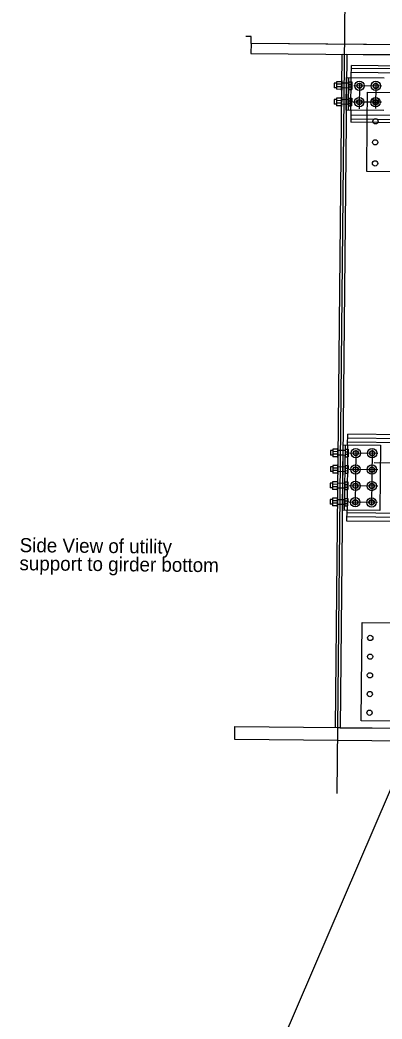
# Model space of a CAD drawing. Extents: x 632312 to 632885, y 378199 to 378534.
# Drawn here: x 632716.99 to 632723.43, y 378443.12 to 378460.93 of the extents above; entities that cross this region are included whole.
import ezdxf

# ---------------------------------------------------------------- set-up
doc = ezdxf.new("R2010")
doc.units = 0
for name, color, linetype in [('B_Boring', 7, 'Continuous'), ('B_Boring Annot', 7, 'Continuous'), ('R_Proposed Const Limits Cut', 7, 'Continuous'), ('R_Shade Removal', 7, 'Continuous'), ('R_Wall', 7, 'Continuous'), ('SHT_Dimensions', 7, 'Continuous'), ('USACE_Easement', 7, 'Continuous')]:
    doc.layers.add(name, color=color, linetype=linetype)

msp = doc.modelspace()

# ---------------------------------------------------------------- linework, layer by layer
at = {"layer": 'B_Boring'}
for p, q in [((632722.888, 378459.902), (632722.89, 378460.114)), ((632733.89, 378460.005), (632722.89, 378460.114)), ((632733.889, 378459.954), (632722.89, 378460.064)), ((632722.585, 378459.8), (632722.584, 378459.717)), ((632722.627, 378459.8), (632722.585, 378459.8)), ((632722.627, 378459.826), (632722.626, 378459.691)), ((632722.71, 378459.825), (632722.627, 378459.826)), ((632722.71, 378459.78), (632722.627, 378459.781)), ((632722.711, 378459.841), (632722.709, 378459.674)), ((632722.721, 378459.841), (632722.711, 378459.841)), ((632722.721, 378459.841), (632722.719, 378459.674)), ((632722.799, 378459.319), (632722.805, 378459.902)), ((632722.805, 378459.902), (632723.472, 378459.896)), ((632722.841, 378459.319), (632722.847, 378459.902)), ((632722.846, 378459.824), (632722.844, 378459.688)), ((632722.845, 378459.779), (632722.897, 378459.778)), ((632722.846, 378459.824), (632722.898, 378459.823)), ((632722.898, 378459.823), (632722.897, 378459.688)), ((632722.626, 378459.717), (632722.584, 378459.717)), ((632722.71, 378459.735), (632722.626, 378459.736)), ((632722.709, 378459.69), (632722.626, 378459.691)), ((632722.719, 378459.674), (632722.709, 378459.674)), ((632722.844, 378459.688), (632722.897, 378459.688)), ((632722.845, 378459.734), (632722.897, 378459.733)), ((632722.582, 378459.509), (632722.581, 378459.425)), ((632722.623, 378459.425), (632722.581, 378459.425)), ((632722.624, 378459.508), (632722.582, 378459.509)), ((632722.624, 378459.534), (632722.623, 378459.399)), ((632722.707, 378459.443), (632722.623, 378459.444)), ((632722.708, 378459.533), (632722.624, 378459.534)), ((632722.707, 378459.488), (632722.624, 378459.489)), ((632722.708, 378459.549), (632722.706, 378459.382)), ((632722.718, 378459.549), (632722.708, 378459.549)), ((632722.718, 378459.549), (632722.716, 378459.382)), ((632722.843, 378459.532), (632722.842, 378459.397)), ((632722.842, 378459.487), (632722.895, 378459.486)), ((632722.842, 378459.442), (632722.894, 378459.441)), ((632722.843, 378459.532), (632722.895, 378459.532)), ((632722.895, 378459.532), (632722.894, 378459.396)), ((632722.706, 378459.398), (632722.623, 378459.399)), ((632722.716, 378459.382), (632722.706, 378459.382)), ((632723.466, 378459.312), (632722.799, 378459.319)), ((632722.842, 378459.397), (632722.894, 378459.396)), ((632722.882, 378459.318), (632722.88, 378459.106)), ((632733.88, 378458.996), (632722.88, 378459.106)), ((632733.88, 378459.047), (632722.881, 378459.156)), ((632723.163, 378458.227), (632723.172, 378459.103)), ((632724.173, 378458.217), (632723.163, 378458.227)), ((632722.823, 378453.354), (632722.825, 378453.546)), ((632733.825, 378453.437), (632722.825, 378453.546)), ((632722.74, 378453.355), (632722.728, 378452.189)), ((632722.74, 378453.355), (632723.406, 378453.349)), ((632722.77, 378452.188), (632722.782, 378453.355)), ((632733.824, 378453.364), (632722.824, 378453.474)), ((632723.406, 378453.349), (632723.395, 378452.182)), ((632722.52, 378453.253), (632722.519, 378453.17)), ((632722.561, 378453.17), (632722.519, 378453.17)), ((632722.562, 378453.253), (632722.52, 378453.253)), ((632722.562, 378453.279), (632722.561, 378453.144)), ((632722.644, 378453.188), (632722.561, 378453.189)), ((632722.645, 378453.278), (632722.562, 378453.279)), ((632722.645, 378453.233), (632722.562, 378453.234)), ((632722.645, 378453.294), (632722.644, 378453.127)), ((632722.656, 378453.294), (632722.645, 378453.294)), ((632722.654, 378453.127), (632722.656, 378453.294)), ((632722.739, 378453.251), (632722.655, 378453.252)), ((632722.78, 378453.232), (632722.832, 378453.231)), ((632722.78, 378453.187), (632722.832, 378453.186)), ((632722.781, 378453.277), (632722.833, 378453.276)), ((632722.833, 378453.276), (632722.831, 378453.141)), ((632722.644, 378453.143), (632722.561, 378453.144)), ((632722.643, 378453.002), (632722.641, 378452.835)), ((632722.653, 378453.002), (632722.643, 378453.002)), ((632722.654, 378453.127), (632722.644, 378453.127)), ((632722.651, 378452.835), (632722.653, 378453.002)), ((632722.738, 378453.168), (632722.655, 378453.169)), ((632722.779, 378453.141), (632722.831, 378453.141)), ((632722.517, 378452.962), (632722.516, 378452.878)), ((632722.558, 378452.878), (632722.516, 378452.878)), ((632722.559, 378452.961), (632722.517, 378452.962)), ((632722.559, 378452.987), (632722.558, 378452.852)), ((632722.642, 378452.896), (632722.558, 378452.897)), ((632722.641, 378452.851), (632722.558, 378452.852)), ((632722.642, 378452.986), (632722.559, 378452.987)), ((632722.642, 378452.941), (632722.559, 378452.942)), ((632722.651, 378452.835), (632722.641, 378452.835)), ((632722.776, 378452.85), (632722.829, 378452.849)), ((632722.777, 378452.94), (632722.829, 378452.939)), ((632722.777, 378452.895), (632722.829, 378452.894)), ((632722.778, 378452.985), (632722.83, 378452.985)), ((632722.83, 378452.985), (632722.829, 378452.849)), ((632722.514, 378452.67), (632722.513, 378452.587)), ((632722.556, 378452.67), (632722.514, 378452.67)), ((632722.556, 378452.696), (632722.555, 378452.56)), ((632722.64, 378452.695), (632722.556, 378452.696)), ((632722.639, 378452.65), (632722.556, 378452.651)), ((632722.64, 378452.71), (632722.638, 378452.544)), ((632722.65, 378452.71), (632722.64, 378452.71)), ((632722.648, 378452.544), (632722.65, 378452.71)), ((632722.774, 378452.648), (632722.827, 378452.648)), ((632722.775, 378452.693), (632722.827, 378452.693)), ((632722.827, 378452.693), (632722.826, 378452.558)), ((632722.555, 378452.586), (632722.513, 378452.587)), ((632722.639, 378452.605), (632722.555, 378452.605)), ((632722.638, 378452.559), (632722.555, 378452.56)), ((632722.648, 378452.544), (632722.638, 378452.544)), ((632722.774, 378452.603), (632722.826, 378452.603)), ((632722.774, 378452.558), (632722.826, 378452.558)), ((632722.511, 378452.378), (632722.511, 378452.295)), ((632722.553, 378452.378), (632722.511, 378452.378)), ((632722.552, 378452.295), (632722.511, 378452.295)), ((632722.553, 378452.404), (632722.552, 378452.269)), ((632722.636, 378452.313), (632722.552, 378452.314)), ((632722.637, 378452.403), (632722.553, 378452.404)), ((632722.636, 378452.358), (632722.553, 378452.359)), ((632722.637, 378452.419), (632722.635, 378452.252)), ((632722.647, 378452.419), (632722.637, 378452.419)), ((632722.646, 378452.252), (632722.647, 378452.419)), ((632722.771, 378452.312), (632722.823, 378452.311)), ((632722.772, 378452.402), (632722.824, 378452.401)), ((632722.772, 378452.357), (632722.824, 378452.356)), ((632722.824, 378452.401), (632722.823, 378452.266)), ((632722.635, 378452.268), (632722.552, 378452.269)), ((632722.646, 378452.252), (632722.635, 378452.252)), ((632723.395, 378452.182), (632722.728, 378452.189)), ((632722.771, 378452.266), (632722.823, 378452.266)), ((632722.81, 378451.996), (632722.812, 378452.188)), ((632733.81, 378451.959), (632722.81, 378452.069)), ((632733.809, 378451.887), (632722.81, 378451.996))]:
    msp.add_line(p, q, dxfattribs=at)
for points in [[(632724.434, 378460.298), (632724.436, 378460.475), (632721.103, 378460.508), (632721.101, 378460.331)], [(632722.69, 378448.314), (632722.606, 378448.315), (632722.726, 378460.315), (632722.809, 378460.314)], [(632724.481, 378448.297), (632724.479, 378448.067), (632720.813, 378448.104), (632720.815, 378448.333)]]:
    msp.add_lwpolyline(points, close=True, dxfattribs=at)
for points in [[(632723.765, 378460.105), (632723.767, 378460.304), (632722.809, 378460.314), (632722.69, 378448.314), (632723.648, 378448.305), (632723.649, 378448.43)], [(632724.455, 378449.825), (632724.441, 378448.422), (632724.441, 378448.422), (632724.441, 378448.422), (632723.066, 378448.436), (632723.083, 378450.186), (632724.098, 378450.175)]]:
    msp.add_lwpolyline(points, dxfattribs=at)
for centre in [(632723.033, 378459.754), (632723.324, 378459.751), (632723.03, 378459.463), (632723.321, 378459.46), (632723.322, 378459.496), (632723.318, 378459.121), (632723.314, 378458.746), (632723.311, 378458.371), (632722.968, 378453.207), (632723.259, 378453.204), (632722.965, 378452.916), (632723.256, 378452.913), (632722.962, 378452.624), (632723.253, 378452.621), (632722.959, 378452.332), (632723.25, 378452.329), (632723.226, 378449.913), (632723.223, 378449.58), (632723.22, 378449.247), (632723.217, 378448.913), (632723.213, 378448.58)]:
    msp.add_circle(centre, 0.0469, dxfattribs=at)
at = {"layer": 'B_Boring Annot'}
for p, q in [((632721.104, 378460.631), (632721.008, 378460.63)), ((632721.103, 378460.508), (632721.104, 378460.631)), ((632724.436, 378460.475), (632721.103, 378460.508))]:
    msp.add_line(p, q, dxfattribs=at)
at = {"layer": 'R_Proposed Const Limits Cut'}
for p, q in [((632733.889, 378459.88), (632722.889, 378459.989)), ((632722.846, 378459.798), (632722.721, 378459.799)), ((632722.882, 378459.318), (632722.888, 378459.902)), ((632722.845, 378459.714), (632722.72, 378459.716)), ((632723.172, 378459.103), (632723.177, 378459.643)), ((632723.177, 378459.643), (632724.552, 378459.63)), ((632722.842, 378459.423), (632722.717, 378459.424)), ((632722.843, 378459.506), (632722.718, 378459.507)), ((632733.881, 378459.121), (632722.882, 378459.231)), ((632722.823, 378453.354), (632722.812, 378452.188)), ((632733.823, 378453.291), (632722.824, 378453.4)), ((632722.78, 378453.251), (632722.739, 378453.251)), ((632722.78, 378453.167), (632722.738, 378453.168)), ((632722.777, 378452.876), (632722.652, 378452.877)), ((632722.778, 378452.959), (632722.653, 378452.96)), ((632722.775, 378452.667), (632722.65, 378452.669)), ((632722.774, 378452.584), (632722.649, 378452.585)), ((632722.771, 378452.292), (632722.646, 378452.294)), ((632722.772, 378452.376), (632722.647, 378452.377)), ((632733.811, 378452.033), (632722.811, 378452.142))]:
    msp.add_line(p, q, dxfattribs=at)
for centre, radius in [((632723.033, 378459.754), 0.0833), ((632723.033, 378459.754), 0.0417), ((632723.324, 378459.751), 0.0833), ((632723.324, 378459.751), 0.0417), ((632723.03, 378459.463), 0.0833), ((632723.03, 378459.463), 0.0417), ((632723.321, 378459.46), 0.0833), ((632723.321, 378459.46), 0.0417), ((632722.968, 378453.207), 0.0833), ((632722.968, 378453.207), 0.0417), ((632723.259, 378453.204), 0.0833), ((632723.259, 378453.204), 0.0417), ((632722.965, 378452.916), 0.0833), ((632723.256, 378452.913), 0.0833), ((632722.965, 378452.916), 0.0417), ((632723.256, 378452.913), 0.0417), ((632722.962, 378452.624), 0.0833), ((632722.962, 378452.624), 0.0417), ((632723.253, 378452.621), 0.0833), ((632723.253, 378452.621), 0.0417), ((632722.959, 378452.332), 0.0833), ((632722.959, 378452.332), 0.0417), ((632723.25, 378452.329), 0.0833), ((632723.25, 378452.329), 0.0417)]:
    msp.add_circle(centre, radius, dxfattribs=at)
at = {"layer": 'R_Shade Removal'}
msp.add_line((632722.636, 378447.138), (632722.786, 378462.203), dxfattribs=at)
at = {"layer": 'R_Wall'}
for p, q in [((632723.033, 378459.808), (632723.029, 378459.345)), ((632723.325, 378459.812), (632723.32, 378459.347)), ((632723.428, 378459.75), (632722.934, 378459.755)), ((632723.426, 378459.459), (632722.916, 378459.464)), ((632723.363, 378453.203), (632722.854, 378453.208)), ((632722.968, 378453.261), (632722.958, 378452.276)), ((632723.26, 378453.265), (632723.25, 378452.271)), ((632723.298, 378453.041), (632724.444, 378453.03)), ((632723.36, 378452.912), (632722.851, 378452.917)), ((632723.358, 378452.62), (632722.848, 378452.625)), ((632723.355, 378452.328), (632722.845, 378452.333))]:
    msp.add_line(p, q, dxfattribs=at)
at = {"layer": 'SHT_Dimensions'}
for p, q in [((632722.781, 378453.277), (632722.779, 378453.141)), ((632722.778, 378452.985), (632722.776, 378452.85)), ((632722.775, 378452.693), (632722.774, 378452.558)), ((632722.772, 378452.402), (632722.771, 378452.266))]:
    msp.add_line(p, q, dxfattribs=at)
at = {"layer": 'USACE_Easement'}
msp.add_line((632721.143, 378441.516), (632733.248, 378469.724), dxfattribs=at)

# ---------------------------------------------------------------- texts
at = {"layer": 'B_Boring'}
for s, p in [('Side View of utility ', (632716.981, 378451.443)), ('support to girder bottom', (632716.978, 378451.12))]:
    msp.add_text(s, height=0.25, rotation=359.4304, dxfattribs=at).set_placement(p)

doc.saveas('drawing.dxf')
